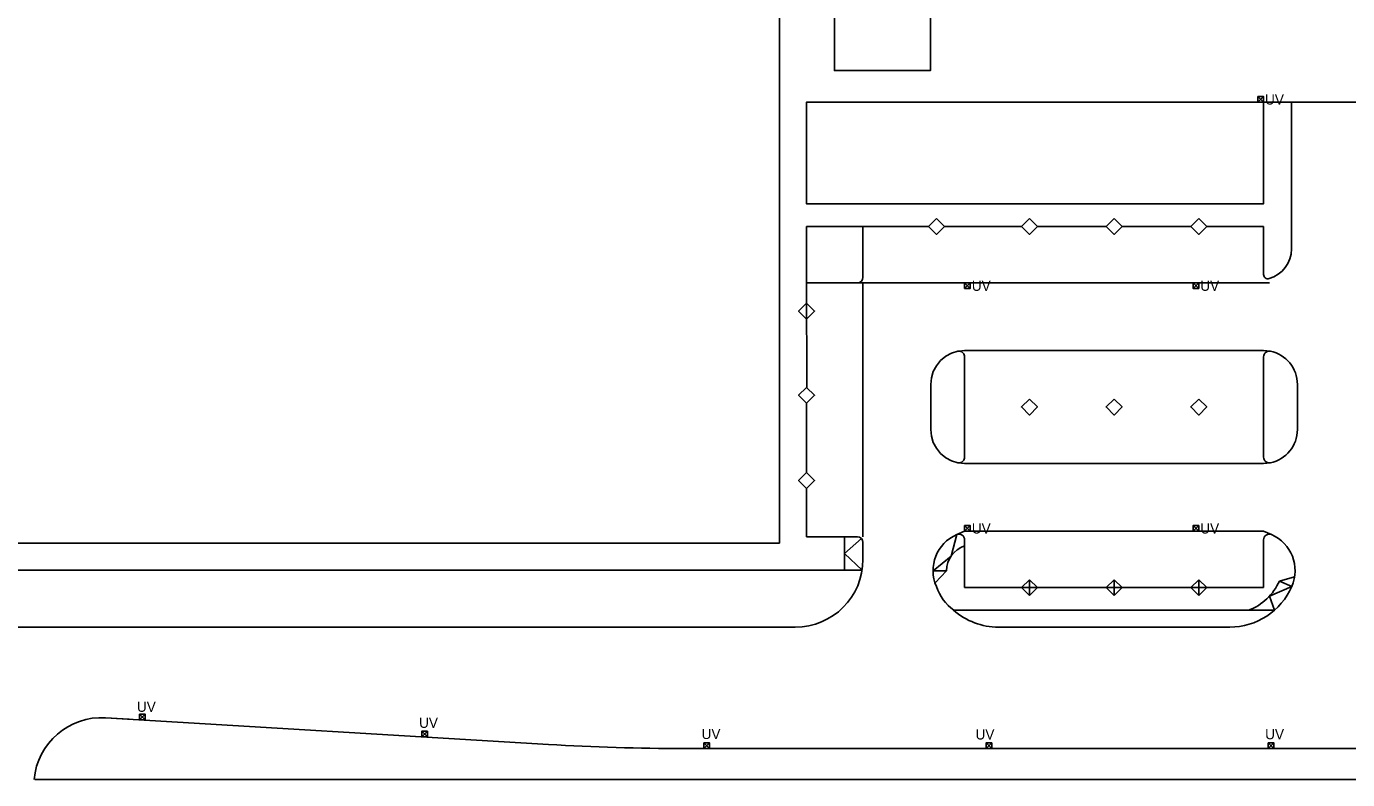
# Model space of a CAD drawing. Extents: x -264222 to -263676, y -1242344 to -1242060.
# Drawn here: x -264039.2 to -263922.1, y -1242315 to -1242248.3 of the extents above; entities that cross this region are included whole.
import ezdxf

# ---------------------------------------------------------------- set-up
doc = ezdxf.new("R2010")
doc.units = 0
doc.layers.add('PROJEKT_DRS_OBRUBNIKY_KOMUNIKACIE', color=7, linetype='Continuous')
doc.layers.add('PROJEKT_DRS_UV_STAVBY', color=7, linetype='Continuous')

msp = doc.modelspace()

# ---------------------------------------------------------------- linework, layer by layer
at = {"layer": 'PROJEKT_DRS_OBRUBNIKY_KOMUNIKACIE'}
for p, q in [((-263929.58, -1242254.98), (-263920.08, -1242254.98)), ((-263927.09, -1242267.98), (-263927.09, -1242254.98)), ((-263959.27, -1242265.98), (-263970.07, -1242265.98)), ((-263965.07, -1242270.48), (-263965.07, -1242265.98)), ((-263957.86, -1242265.98), (-263951.03, -1242265.98)), ((-263949.62, -1242265.98), (-263943.53, -1242265.98)), ((-263942.12, -1242265.98), (-263936.03, -1242265.98)), ((-263934.62, -1242265.98), (-263929.58, -1242265.98)), ((-263929.58, -1242265.98), (-263929.58, -1242270.26)), ((-263970.06, -1242280.24), (-263970.07, -1242270.98)), ((-263965.57, -1242270.98), (-263929.06, -1242270.98)), ((-263965.07, -1242293.48), (-263965.07, -1242270.98)), ((-263957.23, -1242277.22), (-263957.74, -1242277.49)), ((-263956.67, -1242277.04), (-263957.23, -1242277.22)), ((-263956.58, -1242277.03), (-263956.67, -1242277.04)), ((-263956.49, -1242277.04), (-263956.58, -1242277.03)), ((-263956.07, -1242276.98), (-263956.57, -1242277.03)), ((-263956.41, -1242277.06), (-263956.49, -1242277.04)), ((-263956.32, -1242277.1), (-263956.41, -1242277.06)), ((-263956.25, -1242277.15), (-263956.32, -1242277.1)), ((-263956.19, -1242277.21), (-263956.25, -1242277.15)), ((-263956.14, -1242277.28), (-263956.19, -1242277.21)), ((-263956.1, -1242277.36), (-263956.14, -1242277.28)), ((-263929.58, -1242276.98), (-263956.07, -1242276.98)), ((-263929.58, -1242276.98), (-263928.98, -1242277.04)), ((-263958.57, -1242278.32), (-263958.84, -1242278.84)), ((-263958.2, -1242277.87), (-263958.57, -1242278.32)), ((-263957.74, -1242277.49), (-263958.2, -1242277.87)), ((-263956.08, -1242277.44), (-263956.1, -1242277.36)), ((-263956.07, -1242277.53), (-263956.08, -1242277.44)), ((-263956.07, -1242286.43), (-263956.07, -1242277.53)), ((-263929.58, -1242286.43), (-263929.58, -1242277.53)), ((-263959.01, -1242279.4), (-263959.07, -1242279.98)), ((-263958.84, -1242278.84), (-263959.01, -1242279.4)), ((-263959.07, -1242279.98), (-263959.07, -1242283.98)), ((-263926.58, -1242283.98), (-263926.58, -1242279.98)), ((-263926.58, -1242280.48), (-263926.58, -1242283.98)), ((-263970.07, -1242287.78), (-263970.07, -1242281.65)), ((-263959.07, -1242283.98), (-263959.01, -1242284.57)), ((-263959.01, -1242284.57), (-263958.84, -1242285.13)), ((-263958.84, -1242285.13), (-263958.57, -1242285.64)), ((-263958.57, -1242285.64), (-263958.2, -1242286.1)), ((-263958.2, -1242286.1), (-263957.74, -1242286.47)), ((-263957.74, -1242286.47), (-263957.23, -1242286.75)), ((-263956.19, -1242286.76), (-263956.14, -1242286.69)), ((-263956.14, -1242286.69), (-263956.1, -1242286.61)), ((-263956.1, -1242286.61), (-263956.08, -1242286.52)), ((-263956.08, -1242286.52), (-263956.07, -1242286.43)), ((-263957.23, -1242286.75), (-263956.67, -1242286.92)), ((-263956.67, -1242286.92), (-263956.58, -1242286.93)), ((-263956.07, -1242286.98), (-263956.62, -1242286.93)), ((-263956.58, -1242286.93), (-263956.49, -1242286.93)), ((-263956.49, -1242286.93), (-263956.41, -1242286.9)), ((-263956.41, -1242286.9), (-263956.32, -1242286.87)), ((-263956.32, -1242286.87), (-263956.25, -1242286.82)), ((-263956.25, -1242286.82), (-263956.19, -1242286.76)), ((-263929.58, -1242286.98), (-263956.07, -1242286.98)), ((-263929.58, -1242286.98), (-263928.98, -1242286.92)), ((-263970.07, -1242293.48), (-263970.07, -1242289.19)), ((-263970.07, -1242293.48), (-263965.57, -1242293.48)), ((-263966.71, -1242293.48), (-263966.71, -1242296.43)), ((-263956.77, -1242293.28), (-263956.07, -1242292.98)), ((-263929.58, -1242292.98), (-263956.07, -1242292.98)), ((-263956.07, -1242297.98), (-263956.07, -1242293.74)), ((-263929.58, -1242292.98), (-263928.88, -1242293.28)), ((-263929.58, -1242297.98), (-263929.58, -1242293.74)), ((-263965.07, -1242293.98), (-263965.07, -1242295.48)), ((-263928.18, -1242297.4), (-263926.83, -1242297.03)), ((-263929.58, -1242297.98), (-263956.07, -1242297.98)), ((-263950.32, -1242297.28), (-263951.03, -1242297.98)), ((-263951.03, -1242297.98), (-263950.32, -1242298.69)), ((-263949.62, -1242297.98), (-263950.32, -1242297.28)), ((-263950.32, -1242297.28), (-263950.32, -1242298.69)), ((-263950.32, -1242298.69), (-263950.32, -1242297.28)), ((-263950.32, -1242298.69), (-263949.62, -1242297.98)), ((-263942.82, -1242297.28), (-263943.53, -1242297.98)), ((-263943.53, -1242297.98), (-263942.82, -1242298.69)), ((-263942.12, -1242297.98), (-263942.82, -1242297.28)), ((-263942.82, -1242297.28), (-263942.82, -1242298.69)), ((-263942.82, -1242298.69), (-263942.82, -1242297.28)), ((-263942.82, -1242298.69), (-263942.12, -1242297.98)), ((-263935.32, -1242297.28), (-263936.03, -1242297.98)), ((-263936.03, -1242297.98), (-263935.32, -1242298.69)), ((-263934.62, -1242297.98), (-263935.32, -1242297.28)), ((-263935.32, -1242297.28), (-263935.32, -1242298.69)), ((-263935.32, -1242298.69), (-263935.32, -1242297.28)), ((-263935.32, -1242298.69), (-263934.62, -1242297.98)), ((-263928.18, -1242297.4), (-263927.08, -1242297.88)), ((-263928.61, -1242299.98), (-263957.04, -1242299.98)), ((-263971.07, -1242301.48), (-264112.96, -1242301.48)), ((-263932.58, -1242301.48), (-263953.07, -1242301.48)), ((-263992.94, -1242311.87), (-264032.17, -1242309.51)), ((-264032.17, -1242309.51), (-264030.1, -1242309.64)), ((-263980.94, -1242312.23), (-263924.19, -1242312.23)), ((-263842.6, -1242312.24), (-263924.19, -1242312.23)), ((-264038.44, -1242314.98), (-263836.4, -1242314.98))]:
    msp.add_line(p, q, dxfattribs=at)
for points in [[(-264042.57, -1242294.03), (-263972.47, -1242294.03), (-263972.47, -1242187.93), (-264042.57, -1242187.93), (-264042.57, -1242294.03)], [(-263967.6, -1242197.78), (-263959.1, -1242197.78), (-263959.1, -1242252.18), (-263967.6, -1242252.18), (-263967.6, -1242197.78)], [(-263929.58, -1242254.98), (-263970.08, -1242254.98), (-263970.08, -1242263.98), (-263929.58, -1242263.98), (-263929.58, -1242254.98)], [(-263958.57, -1242265.28), (-263957.86, -1242265.98), (-263958.57, -1242266.69), (-263959.27, -1242265.98), (-263958.57, -1242265.28)], [(-263950.32, -1242265.28), (-263949.62, -1242265.98), (-263950.32, -1242266.69), (-263951.03, -1242265.98), (-263950.32, -1242265.28)], [(-263942.82, -1242265.28), (-263942.12, -1242265.98), (-263942.82, -1242266.69), (-263943.53, -1242265.98), (-263942.82, -1242265.28)], [(-263935.32, -1242265.28), (-263934.62, -1242265.98), (-263935.32, -1242266.69), (-263936.03, -1242265.98), (-263935.32, -1242265.28)], [(-263970.07, -1242265.98), (-263970.07, -1242270.98), (-263965.57, -1242270.98)], [(-263970.07, -1242272.78), (-263969.36, -1242273.48), (-263970.07, -1242274.19), (-263970.77, -1242273.48), (-263970.07, -1242272.78)], [(-263970.07, -1242280.24), (-263969.36, -1242280.94), (-263970.07, -1242281.65), (-263970.77, -1242280.94), (-263970.07, -1242280.24)], [(-263950.32, -1242281.28), (-263949.62, -1242281.98), (-263950.32, -1242282.69), (-263951.03, -1242281.98), (-263950.32, -1242281.28)], [(-263942.82, -1242281.28), (-263942.12, -1242281.98), (-263942.82, -1242282.69), (-263943.53, -1242281.98), (-263942.82, -1242281.28)], [(-263935.32, -1242281.28), (-263934.62, -1242281.98), (-263935.32, -1242282.69), (-263936.03, -1242281.98), (-263935.32, -1242281.28)], [(-263970.07, -1242287.78), (-263969.36, -1242288.48), (-263970.07, -1242289.19), (-263970.77, -1242288.48), (-263970.07, -1242287.78)], [(-263965.21, -1242293.63), (-263966.71, -1242294.96), (-263965.14, -1242296.43)], [(-263958.86, -1242296.48), (-263957.27, -1242295.2), (-263956.76, -1242293.27)], [(-263965.14, -1242296.43), (-264120.02, -1242296.43), (-264120.28, -1242296.43)], [(-263958.86, -1242296.48), (-263957.66, -1242296.48), (-263958.69, -1242297.56)], [(-263927.08, -1242297.88), (-263929.05, -1242298.73), (-263928.61, -1242299.98)]]:
    msp.add_lwpolyline(points, dxfattribs=at)
for centre, radius, start, end in [((-263929.8, -1242267.99), 2.7, 285.1069, 0.1973), ((-263929.21, -1242270.25), 0.372, 181.1005, 288.0452), ((-263965.57, -1242270.48), 0.5, 270, 0), ((-263929.08, -1242277.53), 0.5, 78.463, 180), ((-263929.58, -1242279.98), 3, 0, 78.463), ((-263929.58, -1242283.98), 3, 281.537, 0), ((-263929.08, -1242286.43), 0.5, 180, 281.537), ((-263965.57, -1242293.98), 0.5, 0, 90), ((-263955.36, -1242296.48), 3.5, 113.7599, 203.5782), ((-263956.57, -1242293.74), 0.5, 0, 113.7599), ((-263929.08, -1242293.74), 0.5, 66.2401, 180), ((-263930.29, -1242296.48), 3.5, 336.4218, 66.2401), ((-263955.36, -1242296.48), 2.3, 107.9469, 180), ((-263971.07, -1242295.48), 6, 270, 0), ((-263954.44, -1242296.49), 4.35, 198.7173, 233.4513), ((-263932.58, -1242295.48), 6, 270, 336.4218), ((-263932.58, -1242295.48), 4.8, 290.3641, 336.4218), ((-263953.07, -1242295.48), 6, 228.5904, 270), ((-264032.53, -1242315.5), 6, 86.5602, 175.0205), ((-263980.94, -1242112.23), 200, 266.5602, 270)]:
    msp.add_arc(centre, radius, start, end, dxfattribs=at)
at = {"layer": 'PROJEKT_DRS_UV_STAVBY'}
for points in [[(-263930.08, -1242254.98), (-263930.08, -1242254.48), (-263929.58, -1242254.48), (-263929.58, -1242254.98), (-263930.08, -1242254.98), (-263929.58, -1242254.48), (-263930.08, -1242254.48), (-263929.58, -1242254.98)], [(-263956.07, -1242271.48), (-263956.07, -1242270.98), (-263955.57, -1242270.98), (-263955.57, -1242271.48), (-263956.07, -1242271.48), (-263955.57, -1242270.98), (-263956.07, -1242270.98), (-263955.57, -1242271.48)], [(-263935.82, -1242271.48), (-263935.82, -1242270.98), (-263935.32, -1242270.98), (-263935.32, -1242271.48), (-263935.82, -1242271.48), (-263935.32, -1242270.98), (-263935.82, -1242270.98), (-263935.32, -1242271.48)], [(-263956.07, -1242292.98), (-263956.07, -1242292.48), (-263955.57, -1242292.48), (-263955.57, -1242292.98), (-263956.07, -1242292.98), (-263955.57, -1242292.48), (-263956.07, -1242292.48), (-263955.57, -1242292.98)], [(-263935.82, -1242292.98), (-263935.82, -1242292.48), (-263935.32, -1242292.48), (-263935.32, -1242292.98), (-263935.82, -1242292.98), (-263935.32, -1242292.48), (-263935.82, -1242292.48), (-263935.32, -1242292.98)], [(-264029.16, -1242309.7), (-264029.16, -1242309.2), (-264028.66, -1242309.2), (-264028.66, -1242309.7), (-264029.16, -1242309.7), (-264028.66, -1242309.2), (-264029.16, -1242309.2), (-264028.66, -1242309.7)], [(-264004.16, -1242311.2), (-264004.16, -1242310.7), (-264003.66, -1242310.7), (-264003.66, -1242311.2), (-264004.16, -1242311.2), (-264003.66, -1242310.7), (-264004.16, -1242310.7), (-264003.66, -1242311.2)], [(-263979.16, -1242312.23), (-263979.16, -1242311.73), (-263978.66, -1242311.73), (-263978.66, -1242312.23), (-263979.16, -1242312.23), (-263978.66, -1242311.73), (-263979.16, -1242311.73), (-263978.66, -1242312.23)], [(-263954.16, -1242312.23), (-263954.16, -1242311.73), (-263953.66, -1242311.73), (-263953.66, -1242312.23), (-263954.16, -1242312.23), (-263953.66, -1242311.73), (-263954.16, -1242311.73), (-263953.66, -1242312.23)], [(-263929.16, -1242312.23), (-263929.16, -1242311.73), (-263928.66, -1242311.73), (-263928.66, -1242312.23), (-263929.16, -1242312.23), (-263928.66, -1242311.73), (-263929.16, -1242311.73), (-263928.66, -1242312.23)]]:
    msp.add_lwpolyline(points, dxfattribs=at)

# ---------------------------------------------------------------- texts
for p in [(-263929.45, -1242255.19), (-263955.43, -1242271.69), (-263935.19, -1242271.69), (-263955.43, -1242293.19), (-263935.19, -1242293.19), (-264029.4, -1242308.98), (-264004.4, -1242310.4), (-263979.37, -1242311.39), (-263955.1, -1242311.43), (-263929.44, -1242311.41)]:
    msp.add_text('UV', height=0.9, rotation=359.8587, dxfattribs=at).set_placement(p)

doc.saveas('drawing.dxf')
